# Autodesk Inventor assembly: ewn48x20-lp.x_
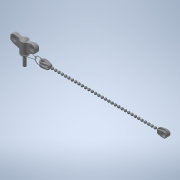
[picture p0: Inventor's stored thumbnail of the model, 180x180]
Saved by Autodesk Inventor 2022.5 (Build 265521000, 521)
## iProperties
Created: 2021-08
Part Number: ewn48x20-lp.x_
Material: 一般
Document SubType Name: Assembly
Designer: ImaoCorp
Sending System: SOLIDWORKS 2019-2019304
MC: AMD64
MC_MODEL: Intel64 Family 6 Model 60 Stepping 3, GenuineIntel
OS: Windows_NT
FRU: Parasolid Version 31.0, build 290,  9- 1-2019
FORMAT: text
GUISE: transmit
KEY: ewn48x20-lp
FILE: ewn48x20-lp.x_t
DATE: Wed Aug 11 15:06:05 2021
Author: ImaoCorp
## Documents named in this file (3)
- X:\14_SW2022-Inv2022\00_全2023-1023新製品(TCC)まで\e\ewn48x20-lp\EWN48X20-LP.iam
- X:\14_SW2022-Inv2022\00_全2023-1023新製品(TCC)まで\e\ewn48x20-lp\ewn48x20-lp_01.ipt
- X:\14_SW2022-Inv2022\00_全2023-1023新製品(TCC)まで\e\ewn48x20-lp\ewn48x20-lp_02.ipt
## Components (2 placed, 2 different names)
1. ewn48x20-lp_01
2. ewn48x20-lp_02
